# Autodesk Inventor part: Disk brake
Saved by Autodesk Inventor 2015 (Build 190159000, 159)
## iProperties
Created: 2015-04
Part Number: Disk brake
Material: Generic
Document SubType Name: Modeling
Designer: Gabriel Cabellos
Density: 1 g/cm^3
Appearance: Default
Author: Gabriel Cabellos
Sending System: SolidWorks 2011
Last Author: Pets
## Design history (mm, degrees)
node "Disk brake.ipt1"
node "Fillet3"
node "Base1"
